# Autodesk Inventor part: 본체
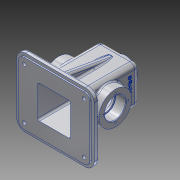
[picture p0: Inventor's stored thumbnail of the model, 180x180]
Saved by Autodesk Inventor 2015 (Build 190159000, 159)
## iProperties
Created: 2016-02
Part Number: 본체
Material: 알루미늄 6061
Document SubType Name: Modeling
Designer: Administrator
Density: 2.7 g/cm^3
Appearance: 알루미늄 - 평지
Mass: 855.968 g
Surface Area: 917.837 cm^2
Volume: 317.025 cm^3
Author: Administrator
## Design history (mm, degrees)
sketch "스케치1"
  geometry: L1 (-65, 57.5)-(65, 57.5); L2 (65, 57.5)-(65, -57.5); L3 (65, -57.5)-(-65, -57.5); L4 (-65, -57.5)-(-65, 57.5); L5 (-65, 57.5)-(65, -57.5); L6 (65, 57.5)-(-65, -57.5); 1 further point
  constraints: 12 end point, 2 midpoint, 2 parallel, 1 horizontal, 1 perpendicular
  dimensions: "d0" = 130 distance between parallel lines of L4 L2; "d1" = 115 distance between parallel lines of L1 L3
extrude "돌출1" new body sketch "스케치1" distance "d2" = 8; taper "d3" = 0 deg
sketch "스케치2"
  geometry: L1 (32.5, -32.5)-(-32.5, -32.5); L2 (-32.5, -32.5)-(-32.5, 32.5); L3 (-32.5, 32.5)-(32.5, 32.5); L4 (32.5, 32.5)-(32.5, -32.5); L5 (32.5, -32.5)-(-32.5, 32.5); L6 (-32.5, -32.5)-(32.5, 32.5); 1 further point
  constraints: 12 end point, 2 midpoint, 2 parallel, 1 horizontal, 1 perpendicular
  dimensions: "d4" = 65 distance between parallel lines of L4 L2; "d5" = 65 distance between parallel lines of L1 L3
extrude "돌출2" join sketch "스케치2" distance "d6" = 100; taper "d7" = 0 deg
sketch "스케치3"
  geometry: L1 (93.069, -32.5)-(8, -47.5); L2 (8, 57.5)-(8, -57.5) reference; L3 (8, -32.5)-(108, -32.5) reference; L4 (0, -57.5)-(8, -57.5) reference; L5 (41.261, 0)-(60.014, 0); L6 (93.069, 32.5)-(8, 47.5); L7 (93.069, -32.5)-(93.069, 32.5); L8 (8, 47.5)-(8, -47.5); 1 further point
  constraints: 10 end point, 2 point on line, 2 symmetric about line, 1 collinear, 1 horizontal, 1 vertical
  dimensions: "d8" = 80 deg angle of L2 L1; "d9" = 10 distance from line of L4 L1.end; "d10" = 0 distance from line of L5 point (0, 0)
extrude "돌출3" join sketch "스케치3" stored distance "d11" = 10; taper "d12" = 0 deg
sketch "스케치5"
  geometry: L1 (-42.5, 5.964)-(42.5, 5.964); L2 (42.5, 5.964)-(42.5, 55.964); L3 (42.5, 55.964)-(-42.5, 55.964); L4 (-42.5, 55.964)-(-42.5, 5.964); L5 (-42.5, 5.964)-(42.5, 55.964); L6 (42.5, 5.964)-(-42.5, 55.964); L7 (65, 0)-(65, 8) reference; L8 (32.5, 8)-(32.5, 108) reference; 2 further points
  constraints: 12 end point, 2 midpoint, 2 parallel, 1 horizontal, 1 perpendicular
  dimensions: "d13" = 0 horizontal distance of point (0, 0) point (0, 30.964); "d16" = 10 distance between parallel lines of L2 L8; "d17" = 50 distance of L1.end L2.end; "d18" = 5.96425 distance from line of L1 point (0, 0)
extrude "돌출4" join sketch "스케치5" stored distance "d19" = 6; taper "d20" = 0 deg
sketch "스케치6"
  geometry: L1 (0, -57.5)-(0, 57.5) reference; C1 r 27.5 at (53, 0); 1 further point
  constraints: 1 centre point
  dimensions: "d21" = 0 vertical distance of point (0, 0) C1.centre; "d22" = 55 diameter of C1; "d23" = 53 distance from line of L1 C1.centre
extrude "돌출5" join sketch "스케치6" stored distance "d24" = 95; taper "d25" = 0 deg
sketch "스케치7"
  geometry: L1 (47.5, 70.5)-(30.5, 70.5); L2 (30.5, 70.5)-(30.5, 68); L3 (30.5, 68)-(0, 68); L4 (-3.111, 53)-(47.5, 53); L5 (47.5, 53)-(47.5, 70.5); L6 (65, 0)-(-65, 0) reference; L7 (47.5, 25.5)-(47.5, 80.5) reference; L8 (-30.5, 68)-(0, 68); L9 (-30.5, 70.5)-(-30.5, 68); L10 (-47.5, 70.5)-(-30.5, 70.5); L11 (-47.5, 53)-(-47.5, 70.5); L12 (-3.111, 53)-(-47.5, 53); L13 (-47.5, 80.5)-(-47.5, 25.5) reference; 1 further point
  constraints: 20 end point, 4 horizontal, 3 perpendicular, 2 vertical
  dimensions: "d26" = 53 distance between parallel lines of L6 L4; "d27" = 15 distance between parallel lines of L4 L3; "d28" = 17.5 distance between parallel lines of L4 L1; "d29" = 17 distance from line of L5 L1.end; "d30" = 0 distance between parallel lines of L5 L7; "d34" = 17.5 distance of L11.start L10.start; "d35" = 17 distance of L10.start L9.start; "d36" = 0 distance between parallel lines of L13 L11
revolve "회전1" sketch "스케치7" stored, may be unused: angle "d37" = 90 deg
node "작업 평면1"
sketch "스케치8"
  geometry: L1 (-27.5, 27.5)-(27.5, 27.5); L2 (27.5, 27.5)-(27.5, -27.5); L3 (27.5, -27.5)-(-27.5, -27.5); L4 (-27.5, -27.5)-(-27.5, 27.5); L5 (-27.5, 27.5)-(27.5, -27.5); L6 (27.5, 27.5)-(-27.5, -27.5); L7 (32.5, -32.5)-(5, -32.5) reference; L8 (32.5, 27.5)-(32.5, -27.5) reference; 3 further points
  constraints: 12 end point, 2 midpoint, 2 parallel, 1 horizontal, 1 perpendicular
  dimensions: "d39" = 5 distance between parallel lines of L7 L3; "d40" = 5 distance between parallel lines of L8 L2
extrude "돌출6" cut sketch "스케치8" stored distance "d41" = 95; taper "d42" = 0 deg
node "작업 평면2"
sketch "스케치9"
  geometry: C1 r 20 at (0, 0); 1 further point
  constraints: 1 centre point, 1 coincident
  dimensions: "d44" = 40 diameter of C1
extrude "돌출7" join sketch "스케치9" stored distance "d45" = 95; taper "d46" = 0 deg
feature "면 기울기1" dims angle "d47" = 5 deg
sketch "스케치10" dims "d48" = 42
  geometry: A1 r 27.5 centre (0, 0) between (3, -27.336) and (-3, -27.336) reference; 6 further points
  constraints: 1 vertical alignment, 8 other
  dimensions: "d49" = 0 horizontal distance of point (0, 0) point (0, 21); "d52" = 360 deg dimension on point (0, 0) point (0, 21) (derived)
hole "구멍1" sketch "스케치10" at (0, 21), (-21, 0), (0, -21), (21, 0) diameter "d54" = 3.242; stored, may be unused: countersink angle "d58" = 90 deg, drill point angle "d60" = 118 deg; dims "d55" = 8, "d56" = 4, "d57" = 2, "d59" = 10
sketch "스케치11"
  geometry: C1 r 10.5 at (0, 0); C2 r 20.875 at (0, 0) reference; 1 further point
  constraints: 1 centre point, 1 concentric
  dimensions: "d61" = 21 diameter of C1
extrude "돌출8" cut sketch "스케치11" stored distance "d62" = 95; taper "d63" = 0 deg
sketch "스케치12" dims "d64" = 29
  geometry: C1 r 20 at (0, 0) reference; 9 further points
  constraints: 2 coincident, 2 horizontal alignment, 2 vertical alignment, 20 other
  dimensions: "d65" = 0 horizontal distance of point (0, 0) point (0, -14.5); "d68" = 360 deg dimension on point (0, 0) point (0, -14.5) (derived)
hole "구멍2" sketch "스케치12" at (0, -14.5), (14.5, 0), (0, 14.5), (-14.5, 0) diameter "d70" = 2.459; stored, may be unused: countersink angle "d74" = 90 deg, drill point angle "d76" = 118 deg; dims "d71" = 7, "d72" = 4, "d73" = 2, "d75" = 9
sketch "스케치13"
  geometry: L1 (-27.5, -15)-(-27.5, 15) reference; L2 (-65, -57.5)-(-65, 57.5) reference; L3 (-65, 57.5)-(65, 57.5) reference; C1 r 7.5 at (-50, 42.5); C2 r 7.5 at (50, 42.5); C3 r 7.5 at (-50, -42.5); C4 r 7.5 at (50, -42.5); 1 further point
  constraints: 4 centre point, 1 horizontal, 1 vertical, 6 other
  dimensions: "d77" = 15 diameter of C1; "d78" = 50 horizontal distance of C1.centre point (0, 0); "d79" = 42.5 vertical distance of point (0, 0) C1.centre; "d82" = 100 distance of C1.centre C2.centre; "d85" = 85 distance of C1.centre C3.centre
extrude "돌출9" join sketch "스케치13" distance "d88" = 11; taper "d89" = 0 deg
sketch "스케치14"
  geometry: L1 (27.5, -27.5)-(-27.5, -27.5) reference; L2 (27.5, 27.5)-(27.5, -27.5) reference; L3 (-27.5, -27.5)-(-27.5, 27.5) reference; L4 (-27.5, 27.5)-(27.5, 27.5) reference; L5 (-60, 52.5)-(60, 52.5); L6 (60, 52.5)-(60, -52.5); L7 (60, -52.5)-(-60, -52.5); L8 (-60, -52.5)-(-60, 52.5); L9 (-60, 52.5)-(60, -52.5); L10 (60, 52.5)-(-60, -52.5); 1 further point
  constraints: 12 end point, 2 midpoint, 2 parallel, 1 horizontal, 1 perpendicular
  dimensions: "d90" = 120 distance between parallel lines of L8 L6; "d91" = 105 distance between parallel lines of L7 L5
extrude "돌출10" join sketch "스케치14" distance "d92" = 2; taper "d93" = 0 deg
fillet "모깎기1" dims "d94" = 10
fillet "모깎기2" dims "d95" = 15
sketch "스케치15"
  geometry: L1 (-100, -15)-(0, -15) reference; L2 (15, 0)-(15, 85) reference; C1 r 3 at (0, 0); C2 r 7.5 at (0, 0) reference; C3 r 3 at (-100, 0); C4 r 3 at (0, 85); C5 r 3 at (-100, 85); 1 further point
  constraints: 4 centre point, 1 concentric, 1 horizontal, 1 vertical, 6 other
  dimensions: "d96" = 6 diameter of C1; "d99" = 100 distance of C1.centre C3.centre; "d102" = 85 distance of C1.centre C4.centre
extrude "돌출11" cut sketch "스케치15" stored distance "d105" = 2; taper "d106" = 0 deg
fillet "모깎기3" dims "d107" = 0.3
fillet "모깎기4" dims "d108" = 8
fillet "모깎기5" dims "d109" = 3
fillet "모깎기6" dims "d110" = 8
fillet "모깎기7" dims "d111" = 3
fillet "모깎기8" dims "d112" = 3
fillet "모깎기10" dims "d114" = 3
fillet "모깎기12" dims "d116" = 3
fillet "모깎기13" dims "d117" = 3
fillet "모깎기14" dims "d118" = 3
chamfer "모따기1" distance "d119" = 1; stored, may be unused: second distance "d120" = 2, angle "d121" = 45 deg
fillet "모깎기15" dims "d122" = 3
fillet "모깎기16" dims "d123" = 3
fillet "모깎기17" dims "d124" = 3
fillet "모깎기18" dims "d125" = 3
fillet "모깎기19" dims "d126" = 3
sketch "스케치16"
  geometry: L1 (-8, 0)-(-8, -92) reference; L2 (4.5, 18)-(44.5, 18) reference; 2 further points
  constraints: 1 other
  dimensions: "d127" = 32.5 distance from line of L1 point (24.5, -8); "d128" = 26 distance from line of L2 point (24.5, -8)
feature "엠보싱1" sketch "스케치16" dims "d129" = 0.5, "d130" = 0
node "솔리드1"
mirror "대칭1"
other parameters: "d38" = -5, "d43" = 118
